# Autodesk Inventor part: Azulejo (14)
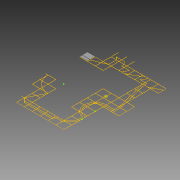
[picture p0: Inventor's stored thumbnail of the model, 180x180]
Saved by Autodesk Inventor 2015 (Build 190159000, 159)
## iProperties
Created: 2015-04
Part Number: Azulejo (14)
Material: Genérico
Document SubType Name: Modeling
Designer: Felipe
Density: 1 g/cm^3
Appearance: Padrão
Author: Felipe
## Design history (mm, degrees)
sketch "Sketch1"
  geometry: L1 (-1510, -7490)-(-1510, -6010); L2 (992.445, 7510)-(992.445, 8990); L3 (1012.445, 7510)-(1012.445, 8990); L4 (-3010, -1490)-(-3010, -10); L5 (-1510, 7490)-(-2990, 7490); L6 (-2990, 10)-(-1510, 10); L7 (-1510, -10)-(-2990, -10); L8 (-1510, -1490)-(-1510, -10); L9 (-10, 9010)-(-10, 10490); L10 (-10, 7510)-(-10, 8990); L11 (-10, 7490)-(-1490, 7490); L12 (-1490, 6010)-(-10, 6010); L13 (-10, 5990)-(-1490, 5990); L14 (-1490, -10)-(-1490, -1490); L15 (-1490, -1490)-(-10, -1490); L16 (-10, -1510)-(-1490, -1510); L17 (-10, -2990)-(-10, -1510); L18 (-10, -5990)-(-10, -4510); L19 (-1490, -7490)-(-10, -7490); L20 (10, 8990)-(10, 7510); L21 (1490, 7510)-(1490, 8990); L22 (10, 6010)-(1490, 6010); L23 (1490, 6010)-(1490, 7490); L24 (1490, 5990)-(10, 5990); L25 (4490, -6010)-(3010, -6010); L26 (10, -1510)-(10, -2990); L27 (10, -3010)-(10, -4490); L28 (10, -4510)-(10, -5990); L29 (10, -5990)-(1490, -5990); L30 (1490, -6010)-(10, -6010); L31 (10, -7490)-(1490, -7490); L32 (2990, 9010)-(2990, 10490); L33 (1510, 8990)-(1510, 7510); L34 (1510, 7510)-(2990, 7510); L35 (2990, 7490)-(1510, 7490); L36 (1510, 7490)-(1510, 6010); L37 (1510, -5990)-(2990, -5990); L38 (2990, -6010)-(1510, -6010); L39 (1510, -7490)-(2990, -7490); L40 (3010, 10490)-(3010, 9010); L41 (3010, 9010)-(4490, 9010); L42 (4490, 8990)-(3010, 8990); L43 (4490, 7490)-(3010, 7490); L44 (4490, 1510)-(4490, 2990); L45 (4490, 10)-(4490, 1490); L46 (4490, -1490)-(4490, -10); L47 (4490, -2990)-(4490, -1510); L48 (3010, -5990)-(4490, -5990); L49 (3010, -7490)-(4490, -7490); L50 (4510, 9010)-(5990, 9010); L51 (5990, 8990)-(4510, 8990); L52 (4510, 7510)-(5990, 7510); L53 (5990, 7490)-(4510, 7490); L54 (4510, 3010)-(5990, 3010); L55 (5990, 2990)-(4510, 2990); L56 (4510, 2990)-(4510, 1510); L57 (4510, 1510)-(5990, 1510); L58 (5990, 1510)-(5990, 1740.185); L59 (5990, 1760.2)-(5990, 2259.8); L60 (5990, 2279.815)-(5990, 2990); L61 (5990, 1490)-(4510, 1490); L62 (4510, 1490)-(4510, 10); L63 (4510, 10)-(5990, 10); L64 (5990, 10)-(5990, 1490)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; A1 r 250 centre (6000, 2010) between (5990, 2259.8) and (5990, 1760.2); A2 r 250 centre (6000, 2010) between (6010, 1760.2) and (6010, 2259.8); A3 r 270 centre (6000, 2010) between (5990, 2279.815) and (5990, 1740.185); A4 r 270 centre (6000, 2010) between (6010, 1740.185) and (6010, 2279.815); A5 r 3010.017 centre (0, 0) between (-1490, -2615.358) and (-346.554, -2990); A6 r 2990.017 centre (0, 0) between (-1490, -2592.316) and (-10, -2990); A7 r 3010.017 centre (0, 0) between (-2603.863, -1510) and (-1510, -2603.863); A8 r 2990.017 centre (0, 0) between (-2580.717, -1510) and (-1510, -2580.717); A9 r 3010.017 centre (0, 0) between (-2990, -346.554) and (-2615.358, -1490); A10 r 2990.017 centre (0, 0) between (-2990, -10) and (-2592.316, -1490); A11 r 2131.367 centre (7500, -1500) between (7490, 631.344) and (6010, 24.017); A12 r 2131.367 centre (7500, -1500) between (5975.983, -10) and (5368.656, -1490); A13 r 2131.367 centre (7500, -1500) between (5368.656, -1510) and (5975.983, -2990); A14 r 2131.367 centre (7500, -1500) between (6010, -3024.017) and (7190, -3608.703); A15 r 1831.367 centre (7500, -1500) between (7490.321, 331.342) and (6463.753, 10); A16 r 1831.367 centre (7500, -1500) between (6435.196, -10) and (6010, -435.196); A17 r 1831.367 centre (7500, -1500) between (5990, -463.753) and (5668.66, -1490); A18 r 1831.367 centre (7500, -1500) between (5668.66, -1510) and (5990, -2536.247); A19 r 1831.367 centre (7500, -1500) between (6010, -2564.804) and (6435.196, -2990); A20 r 1831.367 centre (7500, -1500) between (6463.753, -3010) and (7490, -3331.34); A21 r 2111.367 centre (7500, -1500) between (7490.047, 611.344) and (6024.272, 10); A22 r 2111.367 centre (7500, -1500) between (5990, -24.272) and (5388.656, -1490); A23 r 2111.367 centre (7500, -1500) between (5388.656, -1510) and (5990, -2975.728); A24 r 2111.367 centre (7500, -1500) between (6024.272, -3010) and (7210, -3591.357); A25 r 1811.367 centre (7500, -1500) between (7490.374, 311.342) and (6499.524, 10); A26 r 1811.367 centre (7500, -1500) between (6469.975, -10) and (6010, -469.975); A27 r 1811.367 centre (7500, -1500) between (5990, -499.524) and (5688.66, -1490); A28 r 1811.367 centre (7500, -1500) between (5688.66, -1510) and (5990, -2500.476); A29 r 1811.367 centre (7500, -1500) between (6010, -2530.025) and (6469.975, -2990); A30 r 1811.367 centre (7500, -1500) between (6499.524, -3010) and (7490, -3311.34); A31 r 449.871 centre (7499.449, -4060.672) between (7510, -4510.419) and (7521.546, -4510); 3 further points
  constraints: 1040 end point, 64 point on circle, 31 centre point, 13 point on line, 1 other
extrude "Extrusion1" new body sketch "Sketch1" distance "d0" = 60; taper "d1" = 0 deg
extrude "Extrusion2" new body sketch "Sketch1" distance "d2" = 60; taper "d3" = 0 deg
body "Solid1"
body "Solid2"
